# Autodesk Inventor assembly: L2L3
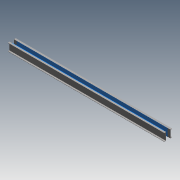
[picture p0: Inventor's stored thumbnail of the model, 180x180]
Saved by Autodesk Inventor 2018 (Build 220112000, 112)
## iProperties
Created: 2018-02
Part Number: L2L3
Document SubType Name: Assembly
Designer: STK
Mass: 1.28048e+06 g
Surface Area: 289407 cm^2
Volume: 163118 cm^3
Density: 7.85 g/cm^3
Author: STK
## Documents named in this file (4)
- D:\SolidWorks\Through Truss\L2L3.iam
- D:\SolidWorks\Through Truss\L0L1 & L1L2\C - Channel.ipt
- D:\SolidWorks\Through Truss\L0L1 & L1L2\C - Channel\C - Channel-02.ipt
- D:\SolidWorks\Through Truss\L1L2 & L2L3\Top Plate.ipt
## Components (4 placed, 3 different names)
1. C - Channel:1
2. C - Channel-02:2 — Flush:4, Mate:3
3. Top Plate:1 — Flush:4, Mate:3, Mate:4, Symmetry:1
4. Top Plate:2 — Mate:4, Symmetry:1
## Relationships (4: Mate 2, Flush 1, Symmetry 1)
- Flush:4: C - Channel-02:2 ↔ Top Plate:1
- Mate:3: C - Channel-02:2 ↔ Top Plate:1
- Mate:4: Top Plate:1 ↔ Top Plate:2
- Symmetry:1: Top Plate:1 ↔ Top Plate:2
